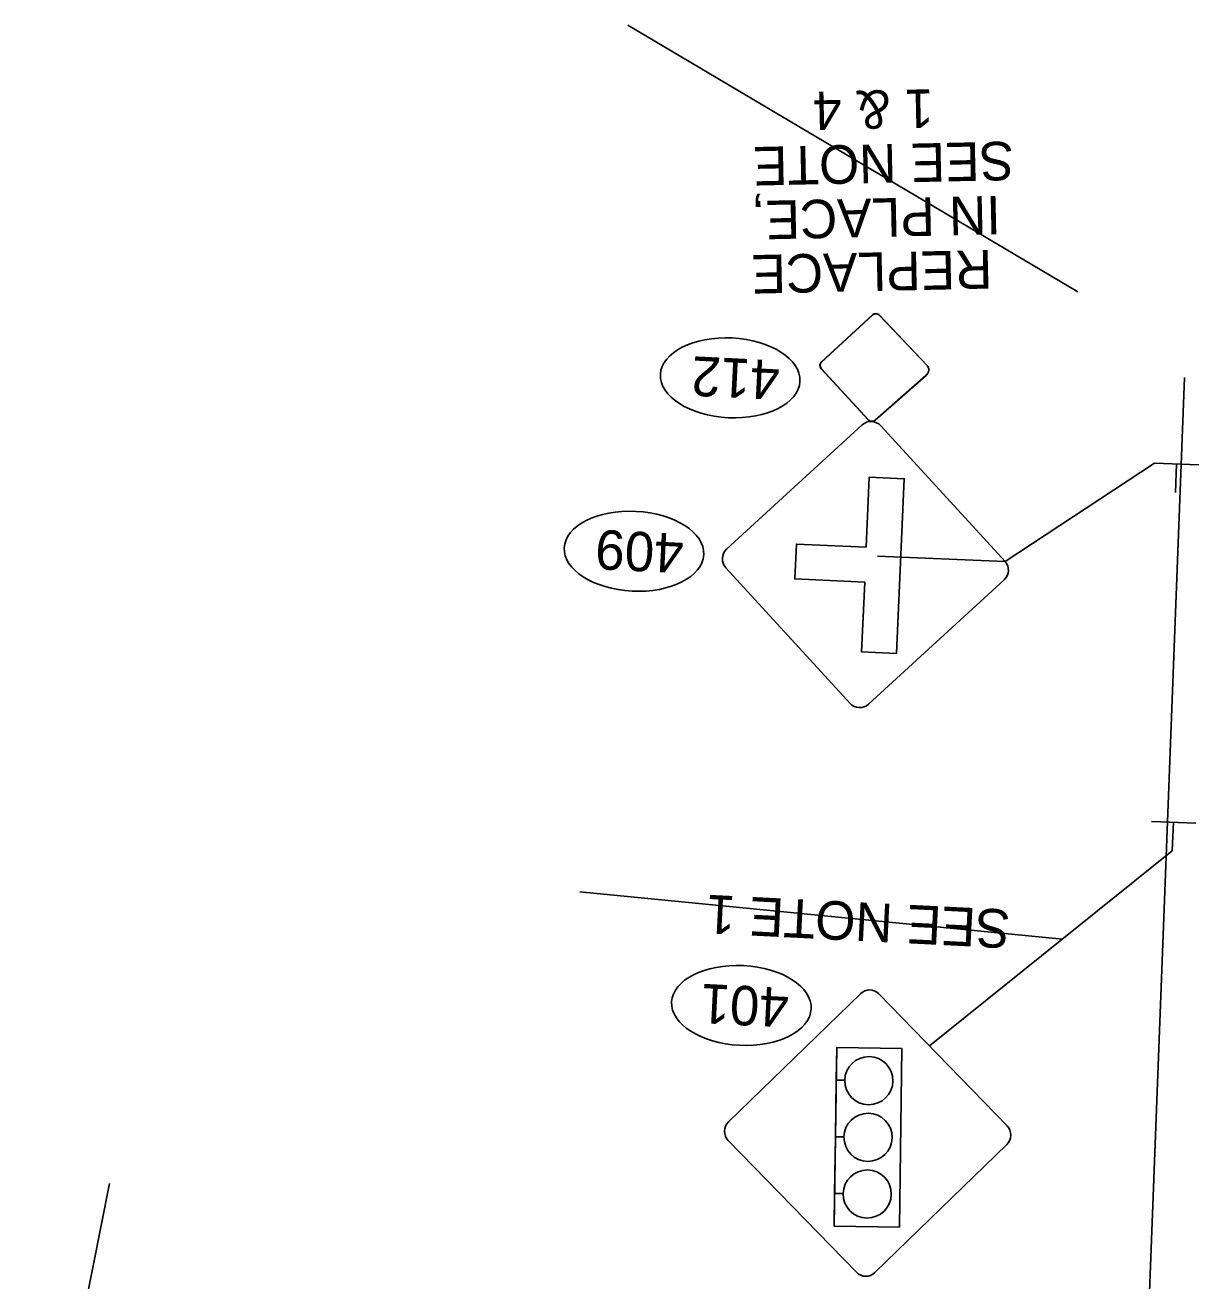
# Model space of a CAD drawing. Extents: x 2096670 to 2098561, y 684033 to 689893.
# Drawn here: x 2097337.4 to 2097702.5, y 687194.8 to 687585.4 of the extents above; entities that cross this region are included whole.
import ezdxf

# ---------------------------------------------------------------- set-up
doc = ezdxf.new("R2010")
doc.units = 0
for name, color, linetype in [('Default', 7, 'Continuous'), ('Exist Sign E No Right Turn CELL', 7, 'Continuous'), ('Exist Sign E Stop Ahead CELL', 7, 'Continuous'), ('Exist Sign E T Intersection Right CELL', 7, 'Continuous'), ('Prop DSN Text', 7, 'Continuous'), ('Prop Sign E One Way_Right CELL', 7, 'Continuous'), ('Prop Sign E Signal Light Ahead CELL', 7, 'Continuous'), ('Scratch_Level_3', 7, 'Continuous'), ('Scratch_Level_4', 7, 'Continuous'), ('Scratch_Level_5', 7, 'Continuous')]:
    doc.layers.add(name, color=color, linetype=linetype)

msp = doc.modelspace()

# ---------------------------------------------------------------- linework, layer by layer
at = {"layer": 'Default'}
msp.add_line((2097694.26, 687328.52), (2097618.72, 687267.88), dxfattribs=at)
at = {"layer": 'Exist Sign E No Right Turn CELL'}
for p, q in [((2097601.02, 687495.26), (2097585.15, 687480.65)), ((2097601.06, 687495.22), (2097585.19, 687480.6)), ((2097601.02, 687495.26), (2097601.06, 687495.22)), ((2097601.06, 687495.22), (2097601.02, 687495.26)), ((2097618.05, 687479.53), (2097603.15, 687495.13)), ((2097618.01, 687479.49), (2097603.19, 687495.17)), ((2097585.06, 687478.47), (2097599.67, 687462.6)), ((2097585.1, 687478.52), (2097599.72, 687462.65)), ((2097601.8, 687462.56), (2097617.64, 687476.45)), ((2097601.85, 687462.51), (2097617.69, 687476.4))]:
    msp.add_line(p, q, dxfattribs=at)
for centre, radius, start, end in [((2097602.06, 687494.13), 1.54, 42.6408, 132.6408), ((2097602.06, 687494.13), 1.48, 42.6408, 132.6408), ((2097586.19, 687479.52), 1.54, 132.6408, 222.6408), ((2097586.19, 687479.52), 1.48, 132.6408, 222.6408), ((2097600.8, 687463.65), 1.54, 222.6408, 312.6408), ((2097600.8, 687463.65), 1.48, 222.6408, 312.6408)]:
    msp.add_arc(centre, radius, start, end, dxfattribs=at)
for major_axis, ratio in [((-1.76, -1.62), 0.833648), ((-1.71, -1.58), 0.884263)]:
    msp.add_ellipse((2097616.29, 687477.91), major_axis=major_axis, ratio=ratio, start_param=1.570796, end_param=3.141593, dxfattribs=at)
at = {"layer": 'Exist Sign E Stop Ahead CELL'}
msp.add_ellipse((2097560.23, 687280.45), major_axis=(21.7, -1.08), ratio=0.571429, dxfattribs=at)
at = {"layer": 'Exist Sign E T Intersection Right CELL'}
for p, q in [((2097597.81, 687461.04), (2097555.62, 687422.38)), ((2097642.24, 687418.6), (2097603.57, 687460.79)), ((2097642.24, 687418.6), (2097688.78, 687449.15)), ((2097555.36, 687416.61), (2097594.03, 687374.42)), ((2097599.79, 687374.17), (2097641.98, 687412.83))]:
    msp.add_line(p, q, dxfattribs=at)
msp.add_lwpolyline([(2097599.07, 687423.04), (2097600.02, 687444.79), (2097610.89, 687444.32), (2097608.52, 687389.95), (2097597.64, 687390.42), (2097598.59, 687412.17), (2097576.85, 687413.12), (2097577.32, 687423.99)], close=True, dxfattribs=at)
msp.add_lwpolyline([(2097599.07, 687423.04), (2097600.02, 687444.79), (2097610.89, 687444.32), (2097608.52, 687389.95), (2097597.64, 687390.42), (2097598.59, 687412.17), (2097576.85, 687413.12), (2097577.32, 687423.99)], close=True, dxfattribs=at)
msp.add_lwpolyline([(2097599.07, 687423.04), (2097600.02, 687444.79), (2097610.89, 687444.32), (2097608.52, 687389.95), (2097597.64, 687390.42), (2097598.59, 687412.17), (2097576.85, 687413.12), (2097577.32, 687423.99)], close=True, dxfattribs=at)
for centre, start, end in [((2097600.56, 687458.03), 42.5016, 132.5016), ((2097558.38, 687419.37), 132.5016, 222.5016), ((2097639.22, 687415.84), 312.5016, 42.5016), ((2097597.04, 687377.18), 222.5016, 312.5016)]:
    msp.add_arc(centre, 4.08, start, end, dxfattribs=at)
at = {"layer": 'Prop DSN Text'}
for p, q in [((2097702.54, 687448.62), (2097688.78, 687449.15)), ((2097695.6, 687448.89), (2097695.26, 687439.97)), ((2097701.54, 687337.17), (2097687.78, 687337.7)), ((2097694.6, 687337.44), (2097694.26, 687328.52))]:
    msp.add_line(p, q, dxfattribs=at)
at = {"layer": 'Prop Sign E Signal Light Ahead CELL'}
for p, q in [((2097597.25, 687284.11), (2097556.21, 687244.23)), ((2097642.9, 687242.99), (2097603.02, 687284.03)), ((2097592.38, 687257.16), (2097592.38, 687257.16)), ((2097592.38, 687257.16), (2097592.38, 687257.16)), ((2097556.13, 687238.46), (2097596.01, 687197.43)), ((2097601.78, 687197.34), (2097642.81, 687237.22))]:
    msp.add_line(p, q, dxfattribs=at)
msp.add_lwpolyline([(2097610.15, 687267.04), (2097589.88, 687267.33), (2097589.09, 687211.8), (2097609.36, 687211.51)], close=True, dxfattribs=at)
for points in [[(2097591.88, 687221.9), (2097589.23, 687221.94), (2097589.09, 687211.8), (2097609.36, 687211.51), (2097610.15, 687267.04), (2097589.88, 687267.33), (2097589.74, 687257.19), (2097592.38, 687257.16)], [(2097591.88, 687221.9), (2097589.23, 687221.94), (2097589.09, 687211.8), (2097609.36, 687211.51), (2097610.15, 687267.04), (2097589.88, 687267.33), (2097589.74, 687257.19), (2097592.38, 687257.16)], [(2097592.38, 687257.16), (2097589.74, 687257.19), (2097589.48, 687239.56), (2097592.13, 687239.53)], [(2097592.38, 687257.16), (2097589.74, 687257.19), (2097589.48, 687239.56), (2097592.13, 687239.53)], [(2097592.13, 687239.53), (2097589.48, 687239.56), (2097589.23, 687221.94), (2097591.88, 687221.9)], [(2097592.13, 687239.53), (2097589.48, 687239.56), (2097589.23, 687221.94), (2097591.88, 687221.9)]]:
    msp.add_lwpolyline(points, dxfattribs=at)
for centre, major_axis, ratio in [((2097556.74, 687475.69), (21.7, -1.08), 0.571429), ((2097526.83, 687421.74), (21.7, -1.08), 0.571429), ((2097560.23, 687280.45), (21.7, -1.08), 0.571429), ((2097599.87, 687257.05), (-0.11, -7.49), 0.999984), ((2097599.62, 687239.42), (-0.11, -7.49), 0.999984), ((2097599.62, 687239.42), (-0.11, -7.49), 0.999984), ((2097599.37, 687221.79), (-0.11, -7.49), 0.999984), ((2097599.37, 687221.79), (-0.11, -7.49), 0.999984)]:
    msp.add_ellipse(centre, major_axis=major_axis, ratio=ratio, dxfattribs=at)
for centre, major_axis, start_param, end_param in [((2097600.09, 687281.18), (-0.06, -4.08), 2.356194, 3.926991), ((2097599.87, 687257.05), (-0.11, -7.49), 4.712482, 10.995574), ((2097599.87, 687257.05), (-0.11, -7.49), 4.712482, 10.995574), ((2097559.06, 687241.3), (-0.06, -4.08), 3.926991, 5.497787), ((2097599.62, 687239.42), (-0.11, -7.49), 4.712482, 10.995574), ((2097599.62, 687239.42), (-0.11, -7.49), 4.712482, 10.995574), ((2097639.97, 687240.15), (-0.06, -4.08), 0.785398, 2.356194), ((2097599.37, 687221.79), (-0.11, -7.49), 4.712482, 10.995574), ((2097599.37, 687221.79), (-0.11, -7.49), 4.712482, 10.995574), ((2097598.94, 687200.27), (-0.06, -4.08), 5.497787, 7.068583)]:
    msp.add_ellipse(centre, major_axis=major_axis, ratio=0.999984, start_param=start_param, end_param=end_param, dxfattribs=at)
at = {"layer": 'Scratch_Level_3'}
for p, q in [((2097664.9, 687502.41), (2097524.95, 687585.42)), ((2097509.99, 687315.81), (2097660.1, 687301.1)), ((2097337.42, 687093.28), (2097363.65, 687225.08))]:
    msp.add_line(p, q, dxfattribs=at)
at = {"layer": 'Scratch_Level_4'}
msp.add_line((2097679.91, 687001.49), (2097698.1, 687475.8), dxfattribs=at)
at = {"layer": 'Scratch_Level_5'}
msp.add_line((2097602.52, 687420.24), (2097642.24, 687418.6), dxfattribs=at)

# ---------------------------------------------------------------- texts
at = {"layer": 'Prop DSN Text'}
for s, rotation, p in [('1 & 4', 181.2349, (2097619.85, 687565.5)), ('SEE NOTE', 181.2349, (2097644.86, 687549.23)), ('IN PLACE,', 181.2349, (2097640.74, 687532.34)), ('REPLACE', 181.2349, (2097638.13, 687515.48)), ('SEE NOTE 1', 177.145, (2097644.09, 687310.18))]:
    msp.add_text(s, height=12, rotation=rotation, dxfattribs=at).set_placement(p)
at = {"layer": 'Prop Sign E One Way_Right CELL'}
for s, p in [('412', (2097572.38, 687481.05)), ('409', (2097542.52, 687427.1)), ('401', (2097575.23, 687285.83))]:
    msp.add_text(s, height=12.265, rotation=177.1414, dxfattribs=at).set_placement(p)

doc.saveas('drawing.dxf')
